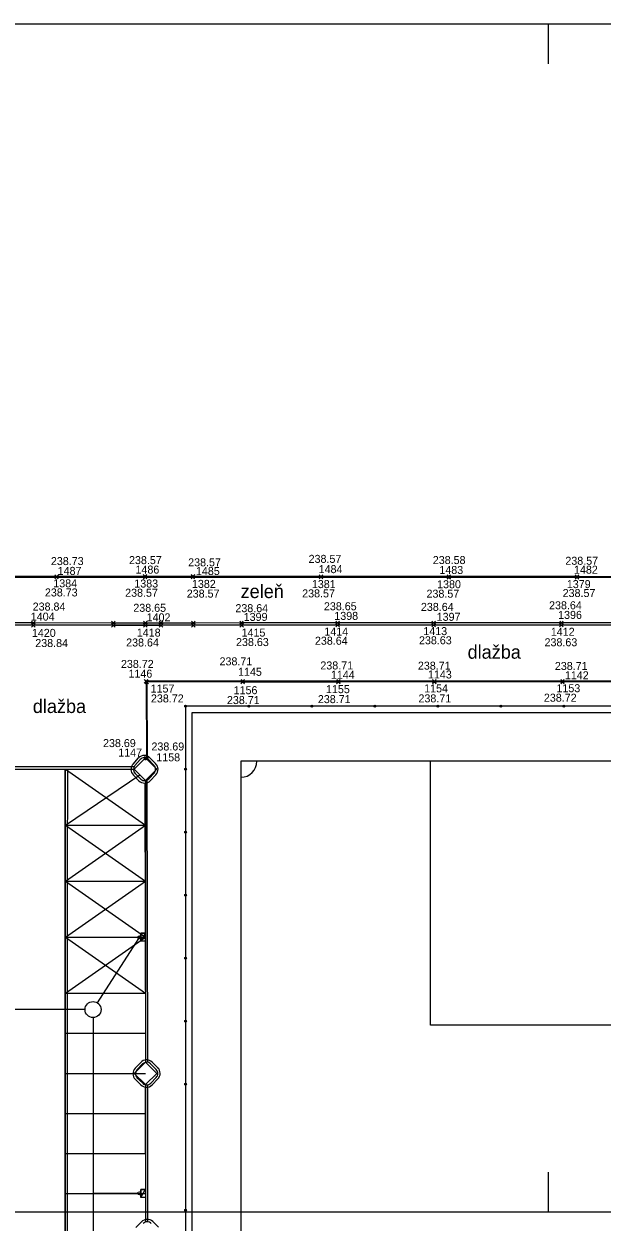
# Model space of a CAD drawing. Extents: x -264205 to -263659, y -1242401 to -1241986.
# Drawn here: x -264128.2 to -264092.1, y -1242219.8 to -1242144.9 of the extents above; entities that cross this region are included whole.
import ezdxf

# ---------------------------------------------------------------- set-up
doc = ezdxf.new("R2010")
doc.units = 0
for name, color, linetype in [('BOD_CISLO_2-1', 7, 'Continuous'), ('BOD_SYMBOL_2-1', 7, 'Continuous'), ('BOD_VYSKA_2-1', 7, 'Continuous'), ('POPIS_2-1', 7, 'Continuous'), ('PROJEKT_OBRUBNIKY_KOMUNIKACIE', 7, 'Continuous'), ('PROJEKT_TDZ_VODOROVNE', 7, 'Continuous'), ('RAM_NA_TLAC_2-1_1-250', 7, 'Continuous'), ('SITUACIA_DSP_2D', 7, 'Continuous'), ('SO_20-3_OBRUBNIKY_DOLNA_HRANA', 7, 'Continuous'), ('SO_20-3_OBRUBNIKY_HORNA_HRANA', 7, 'Continuous'), ('SO_20-4_OBRUBNIKY_HORNA_HRANA', 7, 'Continuous')]:
    doc.layers.add(name, color=color, linetype=linetype)

msp = doc.modelspace()

# ---------------------------------------------------------------- linework, layer by layer
at = {"layer": 'BOD_SYMBOL_2-1'}
for p, q in [((-264126.242, -1242179.588), (-264126.021, -1242179.367)), ((-264126.021, -1242179.588), (-264126.242, -1242179.367)), ((-264126.231, -1242179.543), (-264126.01, -1242179.323)), ((-264126.01, -1242179.543), (-264126.231, -1242179.323)), ((-264120.713, -1242179.536), (-264120.492, -1242179.316)), ((-264120.492, -1242179.536), (-264120.713, -1242179.316)), ((-264120.71, -1242179.586), (-264120.489, -1242179.365)), ((-264120.489, -1242179.586), (-264120.71, -1242179.365)), ((-264117.731, -1242179.59), (-264117.509, -1242179.369)), ((-264117.509, -1242179.59), (-264117.731, -1242179.369)), ((-264117.723, -1242179.542), (-264117.502, -1242179.32)), ((-264117.502, -1242179.542), (-264117.723, -1242179.32)), ((-264109.726, -1242179.546), (-264109.504, -1242179.325)), ((-264109.504, -1242179.546), (-264109.726, -1242179.325)), ((-264109.725, -1242179.589), (-264109.503, -1242179.367)), ((-264109.503, -1242179.589), (-264109.725, -1242179.367)), ((-264101.736, -1242179.556), (-264101.514, -1242179.335)), ((-264101.514, -1242179.556), (-264101.736, -1242179.335)), ((-264101.736, -1242179.596), (-264101.515, -1242179.374)), ((-264101.515, -1242179.596), (-264101.736, -1242179.374)), ((-264093.736, -1242179.549), (-264093.515, -1242179.329)), ((-264093.515, -1242179.549), (-264093.736, -1242179.329)), ((-264093.736, -1242179.596), (-264093.514, -1242179.376)), ((-264093.514, -1242179.596), (-264093.736, -1242179.376)), ((-264127.699, -1242182.448), (-264127.478, -1242182.228)), ((-264127.478, -1242182.448), (-264127.699, -1242182.228)), ((-264127.693, -1242182.592), (-264127.471, -1242182.37)), ((-264127.471, -1242182.592), (-264127.693, -1242182.37)), ((-264122.698, -1242182.599), (-264122.476, -1242182.377)), ((-264122.476, -1242182.599), (-264122.698, -1242182.377)), ((-264122.697, -1242182.455), (-264122.476, -1242182.235)), ((-264122.476, -1242182.455), (-264122.697, -1242182.235)), ((-264120.698, -1242182.455), (-264120.477, -1242182.235)), ((-264120.477, -1242182.455), (-264120.698, -1242182.235)), ((-264120.694, -1242182.597), (-264120.473, -1242182.377)), ((-264120.473, -1242182.597), (-264120.694, -1242182.377)), ((-264119.718, -1242182.457), (-264119.497, -1242182.235)), ((-264119.497, -1242182.457), (-264119.718, -1242182.235)), ((-264119.714, -1242182.6), (-264119.492, -1242182.38)), ((-264119.492, -1242182.6), (-264119.714, -1242182.38)), ((-264117.698, -1242182.453), (-264117.477, -1242182.231)), ((-264117.477, -1242182.453), (-264117.698, -1242182.231)), ((-264117.698, -1242182.596), (-264117.476, -1242182.376)), ((-264117.476, -1242182.596), (-264117.698, -1242182.376)), ((-264114.687, -1242182.448), (-264114.465, -1242182.228)), ((-264114.465, -1242182.448), (-264114.687, -1242182.228)), ((-264114.68, -1242182.592), (-264114.459, -1242182.37)), ((-264114.459, -1242182.592), (-264114.68, -1242182.37)), ((-264108.688, -1242182.443), (-264108.466, -1242182.221)), ((-264108.466, -1242182.443), (-264108.688, -1242182.221)), ((-264108.688, -1242182.59), (-264108.467, -1242182.369)), ((-264108.467, -1242182.59), (-264108.688, -1242182.369)), ((-264102.685, -1242182.586), (-264102.464, -1242182.366)), ((-264102.464, -1242182.586), (-264102.685, -1242182.366)), ((-264102.683, -1242182.44), (-264102.462, -1242182.218)), ((-264102.462, -1242182.44), (-264102.683, -1242182.218)), ((-264094.704, -1242182.583), (-264094.482, -1242182.363)), ((-264094.482, -1242182.583), (-264094.704, -1242182.363)), ((-264094.697, -1242182.44), (-264094.476, -1242182.218)), ((-264094.476, -1242182.44), (-264094.697, -1242182.218)), ((-264120.652, -1242186.093), (-264120.431, -1242185.873)), ((-264120.431, -1242186.093), (-264120.652, -1242185.873)), ((-264120.606, -1242186.137), (-264120.384, -1242185.916)), ((-264120.384, -1242186.137), (-264120.606, -1242185.916)), ((-264114.61, -1242186.141), (-264114.389, -1242185.921)), ((-264114.389, -1242186.141), (-264114.61, -1242185.921)), ((-264114.606, -1242186.095), (-264114.385, -1242185.873)), ((-264114.385, -1242186.095), (-264114.606, -1242185.873)), ((-264108.634, -1242186.14), (-264108.413, -1242185.92)), ((-264108.413, -1242186.14), (-264108.634, -1242185.92)), ((-264108.628, -1242186.095), (-264108.406, -1242185.873)), ((-264108.406, -1242186.095), (-264108.628, -1242185.873)), ((-264102.642, -1242186.093), (-264102.421, -1242185.872)), ((-264102.421, -1242186.093), (-264102.642, -1242185.872)), ((-264102.638, -1242186.137), (-264102.416, -1242185.917)), ((-264102.416, -1242186.137), (-264102.638, -1242185.917)), ((-264094.639, -1242186.088), (-264094.417, -1242185.867)), ((-264094.417, -1242186.088), (-264094.639, -1242185.867)), ((-264094.639, -1242186.133), (-264094.417, -1242185.913)), ((-264094.417, -1242186.133), (-264094.639, -1242185.913)), ((-264120.633, -1242190.896), (-264120.411, -1242190.674)), ((-264120.411, -1242190.896), (-264120.633, -1242190.674)), ((-264120.584, -1242190.917), (-264120.363, -1242190.697)), ((-264120.363, -1242190.917), (-264120.584, -1242190.697))]:
    msp.add_line(p, q, dxfattribs=at)
at = {"layer": 'PROJEKT_OBRUBNIKY_KOMUNIKACIE'}
for p, q in [((-263959.468, -1242179.482), (-264131.568, -1242179.482)), ((-264077.23, -1242179.482), (-264131.568, -1242179.482)), ((-264131.568, -1242179.482), (-263959.468, -1242179.482)), ((-264045.204, -1242182.482), (-264131.568, -1242182.482)), ((-264131.568, -1242191.482), (-264121.275, -1242191.482)), ((-264125.568, -1242270.982), (-264125.568, -1242191.482)), ((-264120.568, -1242192.189), (-264120.568, -1242209.775)), ((-264120.568, -1242211.189), (-264120.568, -1242219.774))]:
    msp.add_line(p, q, dxfattribs=at)
for points in [[(-264117.668, -1242187.932), (-264047.568, -1242187.932), (-264047.568, -1242294.032), (-264117.668, -1242294.032), (-264117.668, -1242187.932)], [(-264120.568, -1242190.775), (-264119.861, -1242191.482), (-264120.568, -1242192.189), (-264121.275, -1242191.482), (-264120.568, -1242190.775)], [(-264120.568, -1242209.775), (-264119.861, -1242210.482), (-264120.568, -1242211.189), (-264121.275, -1242210.482), (-264120.568, -1242209.775)]]:
    msp.add_lwpolyline(points, dxfattribs=at)
at = {"layer": 'PROJEKT_TDZ_VODOROVNE'}
for p, q in [((-264125.568, -1242191.482), (-264120.568, -1242194.982)), ((-264125.568, -1242194.982), (-264120.921, -1242191.836)), ((-264125.568, -1242194.982), (-264120.568, -1242194.982)), ((-264125.568, -1242194.982), (-264120.568, -1242198.482)), ((-264125.568, -1242198.482), (-264120.568, -1242194.982)), ((-264125.568, -1242198.482), (-264120.568, -1242198.482)), ((-264125.568, -1242198.482), (-264120.568, -1242201.982)), ((-264125.568, -1242201.982), (-264120.568, -1242198.482)), ((-264125.568, -1242201.982), (-264120.568, -1242201.982)), ((-264125.568, -1242201.982), (-264120.568, -1242201.982)), ((-264125.568, -1242201.982), (-264120.568, -1242205.482)), ((-264125.568, -1242205.482), (-264120.568, -1242201.982)), ((-264125.568, -1242205.482), (-264120.568, -1242205.482)), ((-264125.568, -1242207.982), (-264120.568, -1242207.982)), ((-264125.568, -1242210.482), (-264120.568, -1242210.482)), ((-264125.568, -1242212.982), (-264120.568, -1242212.982)), ((-264125.568, -1242215.482), (-264120.568, -1242215.482)), ((-264125.568, -1242217.982), (-264120.568, -1242217.982))]:
    msp.add_line(p, q, dxfattribs=at)
at = {"layer": 'RAM_NA_TLAC_2-1_1-250'}
for p, q in [((-264095.413, -1242144.907), (-264095.413, -1242147.407)), ((-264095.413, -1242216.657), (-264095.413, -1242219.157))]:
    msp.add_line(p, q, dxfattribs=at)
msp.add_lwpolyline([(-264147.913, -1242144.907), (-263857.913, -1242144.907), (-263857.913, -1242219.157), (-264147.913, -1242219.157)], close=True, dxfattribs=at)
at = {"layer": 'SITUACIA_DSP_2D'}
for p, q in [((-264077.23, -1242179.482), (-264131.568, -1242179.482)), ((-264131.568, -1242179.482), (-263959.468, -1242179.482)), ((-263959.468, -1242179.482), (-264131.568, -1242179.482)), ((-264045.204, -1242182.482), (-264131.568, -1242182.482)), ((-264118.008, -1242187.532), (-264118.128, -1242187.532)), ((-264118.068, -1242187.592), (-264118.068, -1242187.472)), ((-263972.068, -1242187.532), (-264118.068, -1242187.532)), ((-264118.068, -1242187.532), (-264118.068, -1242294.432)), ((-264114.069, -1242187.532), (-264114.189, -1242187.532)), ((-264114.129, -1242187.592), (-264114.129, -1242187.472)), ((-264110.13, -1242187.532), (-264110.25, -1242187.532)), ((-264110.19, -1242187.592), (-264110.19, -1242187.472)), ((-264106.191, -1242187.532), (-264106.311, -1242187.532)), ((-264106.251, -1242187.592), (-264106.251, -1242187.472)), ((-264102.252, -1242187.532), (-264102.372, -1242187.532)), ((-264102.312, -1242187.592), (-264102.312, -1242187.472)), ((-264098.313, -1242187.532), (-264098.433, -1242187.532)), ((-264098.373, -1242187.592), (-264098.373, -1242187.472)), ((-264094.374, -1242187.532), (-264094.494, -1242187.532)), ((-264094.434, -1242187.592), (-264094.434, -1242187.472)), ((-264117.668, -1242187.932), (-264047.568, -1242187.932)), ((-264117.668, -1242294.032), (-264117.668, -1242187.932)), ((-264121.275, -1242191.482), (-264120.568, -1242190.775)), ((-264120.568, -1242190.775), (-264119.861, -1242191.482)), ((-264120.568, -1242192.189), (-264121.275, -1242191.482)), ((-264119.861, -1242191.482), (-264120.568, -1242192.189)), ((-264118.008, -1242191.47), (-264118.128, -1242191.47)), ((-264118.068, -1242191.41), (-264118.068, -1242191.53)), ((-264050.618, -1242190.982), (-264114.618, -1242190.982)), ((-264114.618, -1242190.982), (-264114.618, -1242290.982)), ((-264102.778, -1242207.482), (-264102.778, -1242190.982)), ((-264120.568, -1242192.189), (-264120.568, -1242209.775)), ((-264118.008, -1242195.407), (-264118.128, -1242195.407)), ((-264118.068, -1242195.347), (-264118.068, -1242195.467)), ((-264118.008, -1242199.345), (-264118.128, -1242199.345)), ((-264118.068, -1242199.285), (-264118.068, -1242199.405)), ((-264120.858, -1242202.232), (-264120.858, -1242201.732)), ((-264120.858, -1242201.732), (-264120.568, -1242201.732)), ((-264120.858, -1242202.232), (-264120.568, -1242201.732)), ((-264120.858, -1242202.232), (-264120.568, -1242201.732)), ((-264120.568, -1242201.732), (-264120.858, -1242201.732)), ((-264120.858, -1242201.732), (-264120.858, -1242202.232)), ((-264120.568, -1242201.732), (-264120.568, -1242202.232)), ((-264121.012, -1242202.066), (-264123.585, -1242206.079)), ((-264120.568, -1242202.232), (-264120.858, -1242202.232)), ((-264118.008, -1242203.282), (-264118.128, -1242203.282)), ((-264118.068, -1242203.222), (-264118.068, -1242203.342)), ((-264176.824, -1242206.476), (-264124.354, -1242206.476)), ((-264123.854, -1242207), (-264123.854, -1242236.976)), ((-264118.008, -1242207.22), (-264118.128, -1242207.22)), ((-264118.068, -1242207.16), (-264118.068, -1242207.28)), ((-264062.458, -1242207.482), (-264102.778, -1242207.482)), ((-264121.275, -1242210.482), (-264120.568, -1242209.775)), ((-264120.568, -1242209.775), (-264119.861, -1242210.482)), ((-264120.568, -1242211.189), (-264121.275, -1242210.482)), ((-264119.861, -1242210.482), (-264120.568, -1242211.189)), ((-264120.568, -1242211.189), (-264120.568, -1242219.774)), ((-264118.008, -1242211.157), (-264118.128, -1242211.157)), ((-264118.068, -1242211.097), (-264118.068, -1242211.217)), ((-264120.86, -1242218.232), (-264120.86, -1242217.732)), ((-264120.86, -1242217.732), (-264120.57, -1242217.732)), ((-264120.86, -1242218.232), (-264120.57, -1242217.732)), ((-264120.86, -1242218.232), (-264120.57, -1242217.732)), ((-264120.57, -1242217.732), (-264120.86, -1242217.732)), ((-264120.86, -1242217.732), (-264120.86, -1242218.232)), ((-264120.57, -1242217.732), (-264120.57, -1242218.232)), ((-264121.058, -1242217.982), (-264123.854, -1242217.982)), ((-264120.57, -1242218.232), (-264120.86, -1242218.232)), ((-264118.008, -1242219.032), (-264118.128, -1242219.032)), ((-264118.068, -1242218.972), (-264118.068, -1242219.092))]:
    msp.add_line(p, q, dxfattribs=at)
for centre, radius in [((-264118.068, -1242187.532), 0.06), ((-264114.129, -1242187.532), 0.06), ((-264110.19, -1242187.532), 0.06), ((-264106.251, -1242187.532), 0.06), ((-264102.312, -1242187.532), 0.06), ((-264098.373, -1242187.532), 0.06), ((-264094.434, -1242187.532), 0.06), ((-264118.068, -1242191.47), 0.06), ((-264118.068, -1242195.407), 0.06), ((-264118.068, -1242199.345), 0.06), ((-264120.958, -1242201.982), 0.1), ((-264118.068, -1242203.282), 0.06), ((-264123.854, -1242206.5), 0.5), ((-264118.068, -1242207.22), 0.06), ((-264118.068, -1242211.157), 0.06), ((-264120.958, -1242217.982), 0.1), ((-264118.068, -1242219.032), 0.06)]:
    msp.add_circle(centre, radius, dxfattribs=at)
msp.add_arc((-264114.618, -1242190.982), 1, 270, 360, dxfattribs=at)
at = {"layer": 'SO_20-3_OBRUBNIKY_DOLNA_HRANA'}
for p, q in [((-264121.354, -1242191.152), (-264121.005, -1242190.771)), ((-264120.296, -1242190.761), (-264119.945, -1242191.127)), ((-264120.984, -1242192.197), (-264121.334, -1242191.846)), ((-264119.928, -1242191.825), (-264120.277, -1242192.2)), ((-264120.624, -1242192.346), (-264120.576, -1242209.647)), ((-264120.869, -1242209.803), (-264121.217, -1242210.165)), ((-264120.164, -1242209.774), (-264119.815, -1242210.129)), ((-264120.858, -1242211.207), (-264121.214, -1242210.853)), ((-264119.796, -1242210.832), (-264120.157, -1242211.208)), ((-264120.561, -1242219.617), (-264120.573, -1242211.348)), ((-264120.826, -1242219.765), (-264121.176, -1242220.119)), ((-264120.126, -1242219.745), (-264119.763, -1242220.105))]:
    msp.add_line(p, q, dxfattribs=at)
for points in [[(-264131.59, -1242194.494), (-264131.592, -1242191.486), (-264121.485, -1242191.482)], [(-264125.573, -1242270.915), (-264125.578, -1242264.895), (-264125.575, -1242255.299), (-264125.581, -1242244.324), (-264125.582, -1242233.844), (-264125.584, -1242219.84), (-264125.593, -1242209.81), (-264125.59, -1242197.798), (-264125.59, -1242191.484)], [(-264125.429, -1242270.662), (-264125.437, -1242264.9), (-264125.431, -1242255.315), (-264125.435, -1242244.34), (-264125.439, -1242233.845), (-264125.44, -1242219.841), (-264125.448, -1242209.814), (-264125.447, -1242197.797), (-264125.435, -1242191.484)]]:
    msp.add_lwpolyline(points, dxfattribs=at)
msp.add_arc((-264120.502, -1242210.139), 0.497, 47.15338, 137.55766, dxfattribs=at)
for centre, major_axis, ratio, start_param, end_param in [((-264120.645, -1242191.116), (-0.299, 0.398), 0.999195, 4.861097, 6.446101), ((-264120.987, -1242191.489), (-0.008, -0.498), 0.999493, 3.986167, 5.529115), ((-264120.286, -1242191.485), (0.366, 0.332), 0.999212, 4.786746, 6.357217), ((-264120.629, -1242191.849), (0.492, -0.07), 0.999786, 4.058846, 5.64051), ((-264120.866, -1242210.507), (-0.486, -0.066), 0.999983, 5.375522, 6.930743), ((-264120.157, -1242210.49), (0.054, 0.494), 0.999945, 4.063089, 5.634789), ((-264120.507, -1242210.857), (0.44, 0.229), 0.999981, 3.445247, 5.016187), ((-264120.466, -1242220.098), (-0.488, 0.046), 0.999933, 4.040271, 5.631388)]:
    msp.add_ellipse(centre, major_axis=major_axis, ratio=ratio, start_param=start_param, end_param=end_param, dxfattribs=at)
at = {"layer": 'SO_20-3_OBRUBNIKY_HORNA_HRANA'}
for p, q in [((-264121.298, -1242191.337), (-264131.738, -1242191.337)), ((-264120.905, -1242190.88), (-264121.24, -1242191.248)), ((-264120.054, -1242191.23), (-264120.406, -1242190.857)), ((-264120.867, -1242192.102), (-264121.218, -1242191.748)), ((-264120.432, -1242209.796), (-264120.475, -1242192.159)), ((-264120.034, -1242191.72), (-264120.375, -1242192.08)), ((-264121.107, -1242210.257), (-264120.759, -1242209.896)), ((-264120.257, -1242209.885), (-264119.911, -1242210.246)), ((-264120.752, -1242211.106), (-264121.107, -1242210.754)), ((-264119.915, -1242210.741), (-264120.25, -1242211.099)), ((-264120.422, -1242219.757), (-264120.426, -1242211.199))]:
    msp.add_line(p, q, dxfattribs=at)
for centre, major_axis, ratio, start_param, end_param in [((-264120.644, -1242191.112), (-0.018, -0.349), 0.999604, 2.442089, 4.03731), ((-264120.974, -1242191.487), (-0.005, -0.358), 0.99766, 3.996827, 5.544901), ((-264120.288, -1242191.485), (0.177, 0.297), 0.998641, 4.503908, 6.079514), ((-264120.631, -1242191.859), (0.338, -0.02), 0.999255, 4.002727, 5.632823), ((-264120.852, -1242210.506), (0.184, -0.304), 0.99963, 3.395005, 4.941577), ((-264120.502, -1242210.148), (-0.353, 0.07), 0.998931, 4.157914, 5.70111), ((-264120.147, -1242210.492), (-0.043, 0.338), 0.998999, 3.764131, 5.388805), ((-264120.504, -1242210.857), (0.35, -0.025), 0.999717, 4.00003, 5.592358), ((-264120.467, -1242220.104), (-0.348, -0.038), 0.999249, 3.8025, 5.417886)]:
    msp.add_ellipse(centre, major_axis=major_axis, ratio=ratio, start_param=start_param, end_param=end_param, dxfattribs=at)
at = {"layer": 'SO_20-4_OBRUBNIKY_HORNA_HRANA'}
for points in [[(-264042.383, -1242179.442), (-264049.652, -1242179.445), (-264056.638, -1242179.441), (-264063.632, -1242179.437), (-264070.626, -1242179.438), (-264077.626, -1242179.445), (-264085.626, -1242179.449), (-264093.626, -1242179.439), (-264101.625, -1242179.445), (-264109.615, -1242179.435), (-264117.612, -1242179.431), (-264120.602, -1242179.426), (-264126.121, -1242179.433), (-264131.733, -1242179.426)], [(-264045.552, -1242182.335), (-264054.544, -1242182.343), (-264062.556, -1242182.34), (-264070.561, -1242182.336), (-264078.574, -1242182.331), (-264086.572, -1242182.331), (-264094.586, -1242182.329), (-264102.573, -1242182.329), (-264108.577, -1242182.332), (-264114.576, -1242182.338), (-264117.588, -1242182.342), (-264119.607, -1242182.346), (-264120.588, -1242182.345), (-264122.586, -1242182.345), (-264127.589, -1242182.338), (-264131.6, -1242182.327), (-264131.589, -1242179.471)], [(-264042.533, -1242179.487), (-264049.65, -1242179.49), (-264056.635, -1242179.487), (-264063.63, -1242179.486), (-264070.632, -1242179.485), (-264077.626, -1242179.49), (-264085.624, -1242179.493), (-264093.625, -1242179.486), (-264101.626, -1242179.485), (-264109.614, -1242179.478), (-264117.62, -1242179.479), (-264120.6, -1242179.475), (-264126.132, -1242179.477), (-264131.589, -1242179.471)], [(-264045.568, -1242182.477), (-264054.55, -1242182.489), (-264062.559, -1242182.483), (-264070.564, -1242182.48), (-264078.567, -1242182.474), (-264086.573, -1242182.479), (-264094.593, -1242182.473), (-264102.574, -1242182.476), (-264108.578, -1242182.479), (-264114.569, -1242182.481), (-264117.587, -1242182.486), (-264119.603, -1242182.49), (-264120.584, -1242182.487), (-264122.587, -1242182.488), (-264127.582, -1242182.481), (-264131.601, -1242182.479), (-264131.604, -1242183.314), (-264131.618, -1242187.312), (-264131.63, -1242191.337)], [(-264052.662, -1242185.992), (-264054.609, -1242185.985), (-264062.596, -1242185.988), (-264070.563, -1242185.986), (-264078.563, -1242185.989), (-264086.55, -1242185.979), (-264094.528, -1242185.977), (-264102.531, -1242185.982), (-264108.517, -1242185.984), (-264114.496, -1242185.984), (-264120.541, -1242185.983), (-264120.522, -1242190.785)], [(-264052.656, -1242186.038), (-264054.607, -1242186.03), (-264062.596, -1242186.031), (-264070.567, -1242186.033), (-264078.568, -1242186.034), (-264086.548, -1242186.025), (-264094.528, -1242186.023), (-264102.527, -1242186.027), (-264108.524, -1242186.03), (-264114.499, -1242186.031), (-264120.495, -1242186.026), (-264120.474, -1242190.807)]]:
    msp.add_lwpolyline(points, dxfattribs=at)

# ---------------------------------------------------------------- texts
at = {"layer": 'BOD_CISLO_2-1'}
for s, p in [('1486', (-264121.201, -1242179.253)), ('1484', (-264109.759, -1242179.225)), ('1483', (-264102.219, -1242179.277)), ('1482', (-264093.808, -1242179.261)), ('1487', (-264126.062, -1242179.335)), ('1485', (-264117.425, -1242179.344)), ('1384', (-264126.335, -1242180.111)), ('1383', (-264121.274, -1242180.124)), ('1382', (-264117.674, -1242180.147)), ('1381', (-264110.183, -1242180.16)), ('1380', (-264102.359, -1242180.168)), ('1379', (-264094.256, -1242180.16)), ('1404', (-264127.742, -1242182.191)), ('1402', (-264120.504, -1242182.238)), ('1399', (-264114.442, -1242182.211)), ('1398', (-264108.78, -1242182.146)), ('1397', (-264102.386, -1242182.204)), ('1396', (-264094.8, -1242182.085)), ('1420', (-264127.672, -1242183.209)), ('1418', (-264121.118, -1242183.19)), ('1415', (-264114.574, -1242183.191)), ('1414', (-264109.402, -1242183.123)), ('1413', (-264103.221, -1242183.099)), ('1412', (-264095.256, -1242183.14)), ('1146', (-264121.638, -1242185.757)), ('1145', (-264114.796, -1242185.642)), ('1144', (-264108.994, -1242185.827)), ('1143', (-264102.932, -1242185.807)), ('1142', (-264094.378, -1242185.858)), ('1157', (-264120.258, -1242186.688)), ('1156', (-264115.071, -1242186.789)), ('1155', (-264109.301, -1242186.725)), ('1154', (-264103.169, -1242186.676)), ('1153', (-264094.903, -1242186.666)), ('1147', (-264122.278, -1242190.687)), ('1158', (-264119.902, -1242190.985))]:
    msp.add_text(s, height=0.5, dxfattribs=at).set_placement(p)
at = {"layer": 'BOD_VYSKA_2-1'}
for s, p in [('238.57', (-264110.386, -1242178.583)), ('238.73', (-264126.485, -1242178.721)), ('238.57', (-264121.605, -1242178.661)), ('238.57', (-264117.91, -1242178.799)), ('238.58', (-264102.629, -1242178.658)), ('238.57', (-264094.348, -1242178.702)), ('238.73', (-264126.86, -1242180.681)), ('238.57', (-264121.847, -1242180.701)), ('238.57', (-264117.998, -1242180.753)), ('238.57', (-264110.788, -1242180.741)), ('238.57', (-264103.021, -1242180.759)), ('238.57', (-264094.517, -1242180.719)), ('238.84', (-264127.623, -1242181.563)), ('238.65', (-264109.43, -1242181.545)), ('238.64', (-264095.366, -1242181.483)), ('238.65', (-264121.336, -1242181.642)), ('238.64', (-264114.96, -1242181.664)), ('238.64', (-264103.371, -1242181.585)), ('238.64', (-264121.785, -1242183.808)), ('238.63', (-264114.92, -1242183.782)), ('238.64', (-264109.991, -1242183.699)), ('238.63', (-264103.492, -1242183.67)), ('238.63', (-264095.648, -1242183.795)), ('238.84', (-264127.461, -1242183.843)), ('238.72', (-264122.109, -1242185.149)), ('238.71', (-264115.95, -1242184.988)), ('238.71', (-264109.652, -1242185.244)), ('238.71', (-264103.559, -1242185.257)), ('238.71', (-264095.003, -1242185.276)), ('238.72', (-264120.235, -1242187.304)), ('238.71', (-264115.488, -1242187.407)), ('238.71', (-264109.809, -1242187.348)), ('238.71', (-264103.524, -1242187.302)), ('238.72', (-264095.689, -1242187.259)), ('238.69', (-264123.229, -1242190.095)), ('238.69', (-264120.204, -1242190.307))]:
    msp.add_text(s, height=0.5, dxfattribs=at).set_placement(p)
at = {"layer": 'POPIS_2-1'}
for s, p in [('zeleň', (-264114.633, -1242180.784)), ('dlažba', (-264100.454, -1242184.573)), ('dlažba', (-264127.613, -1242187.966))]:
    msp.add_text(s, height=0.8438, dxfattribs=at).set_placement(p)

doc.saveas('drawing.dxf')
